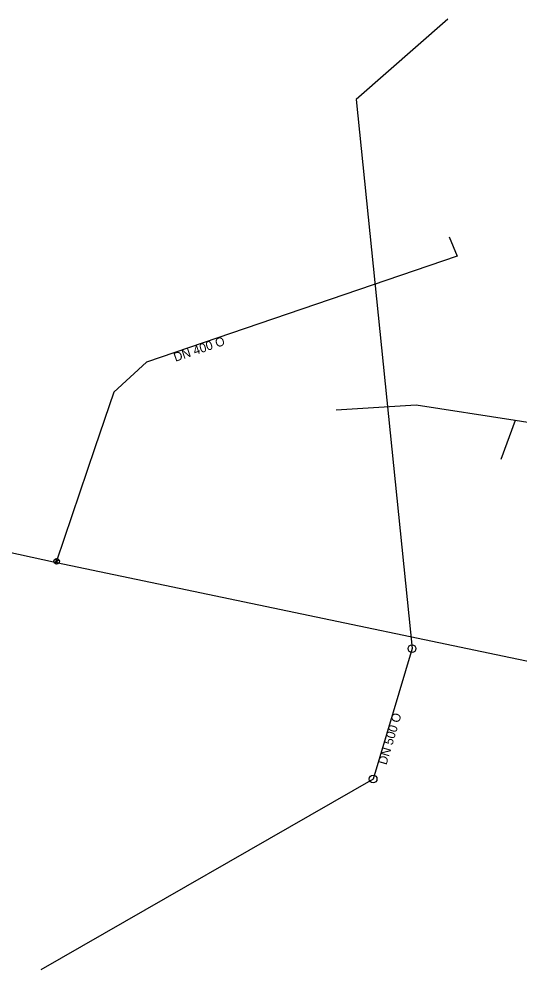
# Model space of a CAD drawing. Extents: x -451355 to -449353, y -1101368 to -1101089.
# Drawn here: x -449571.2 to -449481.2, y -1101354.5 to -1101183.7 of the extents above; entities that cross this region are included whole.
import ezdxf

# ---------------------------------------------------------------- set-up
doc = ezdxf.new("R2010")
doc.units = 0
for name, color, linetype in [('_odpadni_voda_', 7, 'Continuous'), ('_pripojka_prevzato_z_dokumentace_', 7, 'Continuous'), ('_voda_smvak_prevzato_z_dokumentace_', 7, 'Continuous'), ('_vodovodni_chranicka_', 7, 'Continuous'), ('Default', 7, 'Continuous'), ('MoLevel 27', 7, 'Continuous'), ('MoLevel 30', 7, 'Continuous'), ('MoLevel 35', 7, 'Continuous'), ('MoLevel 46', 7, 'Continuous')]:
    doc.layers.add(name, color=color, linetype=linetype)

# ---------------------------------------------------------------- blocks, each defined once
blk = doc.blocks.new('_uzaver_')
at = {"layer": 'Default'}
for p, q in [((-0.000035, -0.000035), (0.000035, 0.000035)), ((0.000035, -0.000035), (-0.000035, 0.000035))]:
    blk.add_line(p, q, dxfattribs=at)
for radius in [0.00005, 0.0000025]:
    blk.add_circle((0, 0), radius, dxfattribs=at)
blk = doc.blocks.new('_sachta_voda_')
at = {"layer": 'Default'}
blk.add_circle((0, 0), 0.000035, dxfattribs=at)

msp = doc.modelspace()

# ---------------------------------------------------------------- linework, layer by layer
at = {"layer": '_odpadni_voda_'}
msp.add_lwpolyline([(-449494.18, -1101183.7), (-449510.66, -1101198.13), (-449500.63, -1101296.78), (-449507.62, -1101320.21), (-449567.28, -1101354.5)], dxfattribs=at)
at = {"layer": '_pripojka_prevzato_z_dokumentace_'}
msp.add_line((-449482.13, -1101255.83), (-449484.7, -1101262.79), dxfattribs=at)
for points in [[(-449482.13, -1101255.83), (-449499.88, -1101253.03), (-449514.24, -1101253.93)], [(-449455.14, -1101257.84), (-449458.96, -1101259.45), (-449482.13, -1101255.83)]]:
    msp.add_lwpolyline(points, dxfattribs=at)
at = {"layer": '_voda_smvak_prevzato_z_dokumentace_'}
msp.add_line((-449564.45, -1101281.1), (-449564.49, -1101281.4), dxfattribs=at)
for points in [[(-449493.97, -1101222.8), (-449492.53, -1101226.31), (-449548.33, -1101245.36), (-449554.19, -1101250.7), (-449557.61, -1101260.72), (-449564.45, -1101281.1)], [(-449564.49, -1101281.4), (-449698.07, -1101252.11), (-449883.18, -1101229.61), (-449925.88, -1101227.01), (-449951.55, -1101226.31), (-449972.21, -1101225.79), (-449993.64, -1101225.6), (-450007.68, -1101225.99), (-450015.78, -1101225.72), (-450021.06, -1101225.6), (-450023.29, -1101225.59), (-450026.26, -1101226.9)], [(-449353.08, -1101265.82), (-449415.52, -1101288.81), (-449427.62, -1101291.49), (-449432.96, -1101292.67), (-449446.62, -1101306.05), (-449564.49, -1101281.4)]]:
    msp.add_lwpolyline(points, dxfattribs=at)
at = {"layer": '_vodovodni_chranicka_'}
msp.add_line((-449510.66, -1101198.13), (-449500.63, -1101296.78), dxfattribs=at)

# ---------------------------------------------------------------- block references
at = {"layer": 'MoLevel 27', "xscale": 10000, "yscale": 10000, "rotation": 71.4370975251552}
msp.add_blockref('_uzaver_', (-449564.45, -1101281.1), dxfattribs=at)
at = {"layer": 'MoLevel 30', "xscale": 20000, "yscale": 20000}
for p in [(-449500.63, -1101296.78), (-449507.62, -1101320.21)]:
    msp.add_blockref('_sachta_voda_', p, dxfattribs=at)

# ---------------------------------------------------------------- texts
at = {"layer": 'MoLevel 35'}
msp.add_text('DN 500 O', height=1.605, rotation=73.3957, dxfattribs=at).set_placement((-449505.22, -1101317.77))
at = {"layer": 'MoLevel 46'}
msp.add_text('DN 400 O', height=1.605, rotation=18.8498, dxfattribs=at).set_placement((-449543.12, -1101245.28))

doc.saveas('drawing.dxf')
